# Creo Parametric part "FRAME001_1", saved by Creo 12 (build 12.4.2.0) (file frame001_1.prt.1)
Units: Custom; MM, KILOGRAM, SECS

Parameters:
  PTC_WM_ITERATION = "0"
  PTC_WM_VERSION = "-.0"
  PTC_WM_LIFECYCLE_STATE = "In Work"
  PTC_WM_LIFECYCLE = "MO_CADDocument"
  PTC_WM_CREATED_BY = "Maximilian Roepper (Z0017RMS: MO)"
  PTC_WM_CREATED_ON = "18-Sep-26 11:36:42 AM"
  PTC_WM_MODIFIED_BY = "Maximilian Roepper (Z0017RMS: MO)"
  PTC_WM_MODIFIED_ON = "18-Sep-26 11:36:46 AM"
  PDMLINKNUMBER = "PDM000071454798"
  PTC_WM_NAME = "frame001_1.prt"
  PTC_WM_NUMBER = "PDM000071454798"

Other parameters: WEIGHT, WEIGHT_FACTOR, WEIGHT_ADD, _MASS_TEMP, _DIFF_TEMP, MC_ERRORS, SUPPLIER

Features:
  1. coordinate system
  2. datum plane "PRT_YZ"
  3. datum plane "PRT_XY"
  4. datum plane "PRT_XZ"
  5. coordinate system
  6. datum axis
  7. datum axis
  8. datum axis
  9. coordinate system
  10. imported feature

Other named items: PRT, SIEMENS_MO, DRW_VIEW_ORG, PRT_X, PRT_Y, PRT_Z, CS0, ROUGH_GROB

Layers: 00_STD_CSYS-KSYS, 01_STD_PLANES-EBENEN, 02_STD_AXES-ACHSEN, 03_STD_CSYS-KSYS, 24_IMPORT_FEAT-IMPORT_KE

Surfaces: 130 plane, 3 cylinder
